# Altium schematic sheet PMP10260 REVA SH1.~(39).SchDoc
size 431 x 279 mm; Date: Not shown in title block; ApprovedBy: Not shown in title block; CheckedBy: Not shown in title block; Author: Not shown in title block; CompanyName: Not shown in title block; Engineer: Not shown in title block; Organization: Not shown in title block; Address1: Not shown in title block; Address2: Not shown in title block; Address3: Not shown in title block; Address4: Not shown in title block; DocumentNumber: 1; Revision: Use project parameter SCH_Rev; SheetNumber: 1; SheetTotal: 4; PageSetup: Record=PageOptions|CenterHorizontal=True|CenterVertical=True|PrintScale=1.00|XCorrection=1.00|YCorrection=1.00|PrintKind=0|BorderSize=5000000|LeftOffset=0|BottomOffset=0|Orientation=2|PaperLength=1000|PaperWidth=1000|Scale=100|PaperSource=15|PrintQuality=600|MediaType=1|DitherType=10|PaperKind=Letter|PrintScaleMode=1
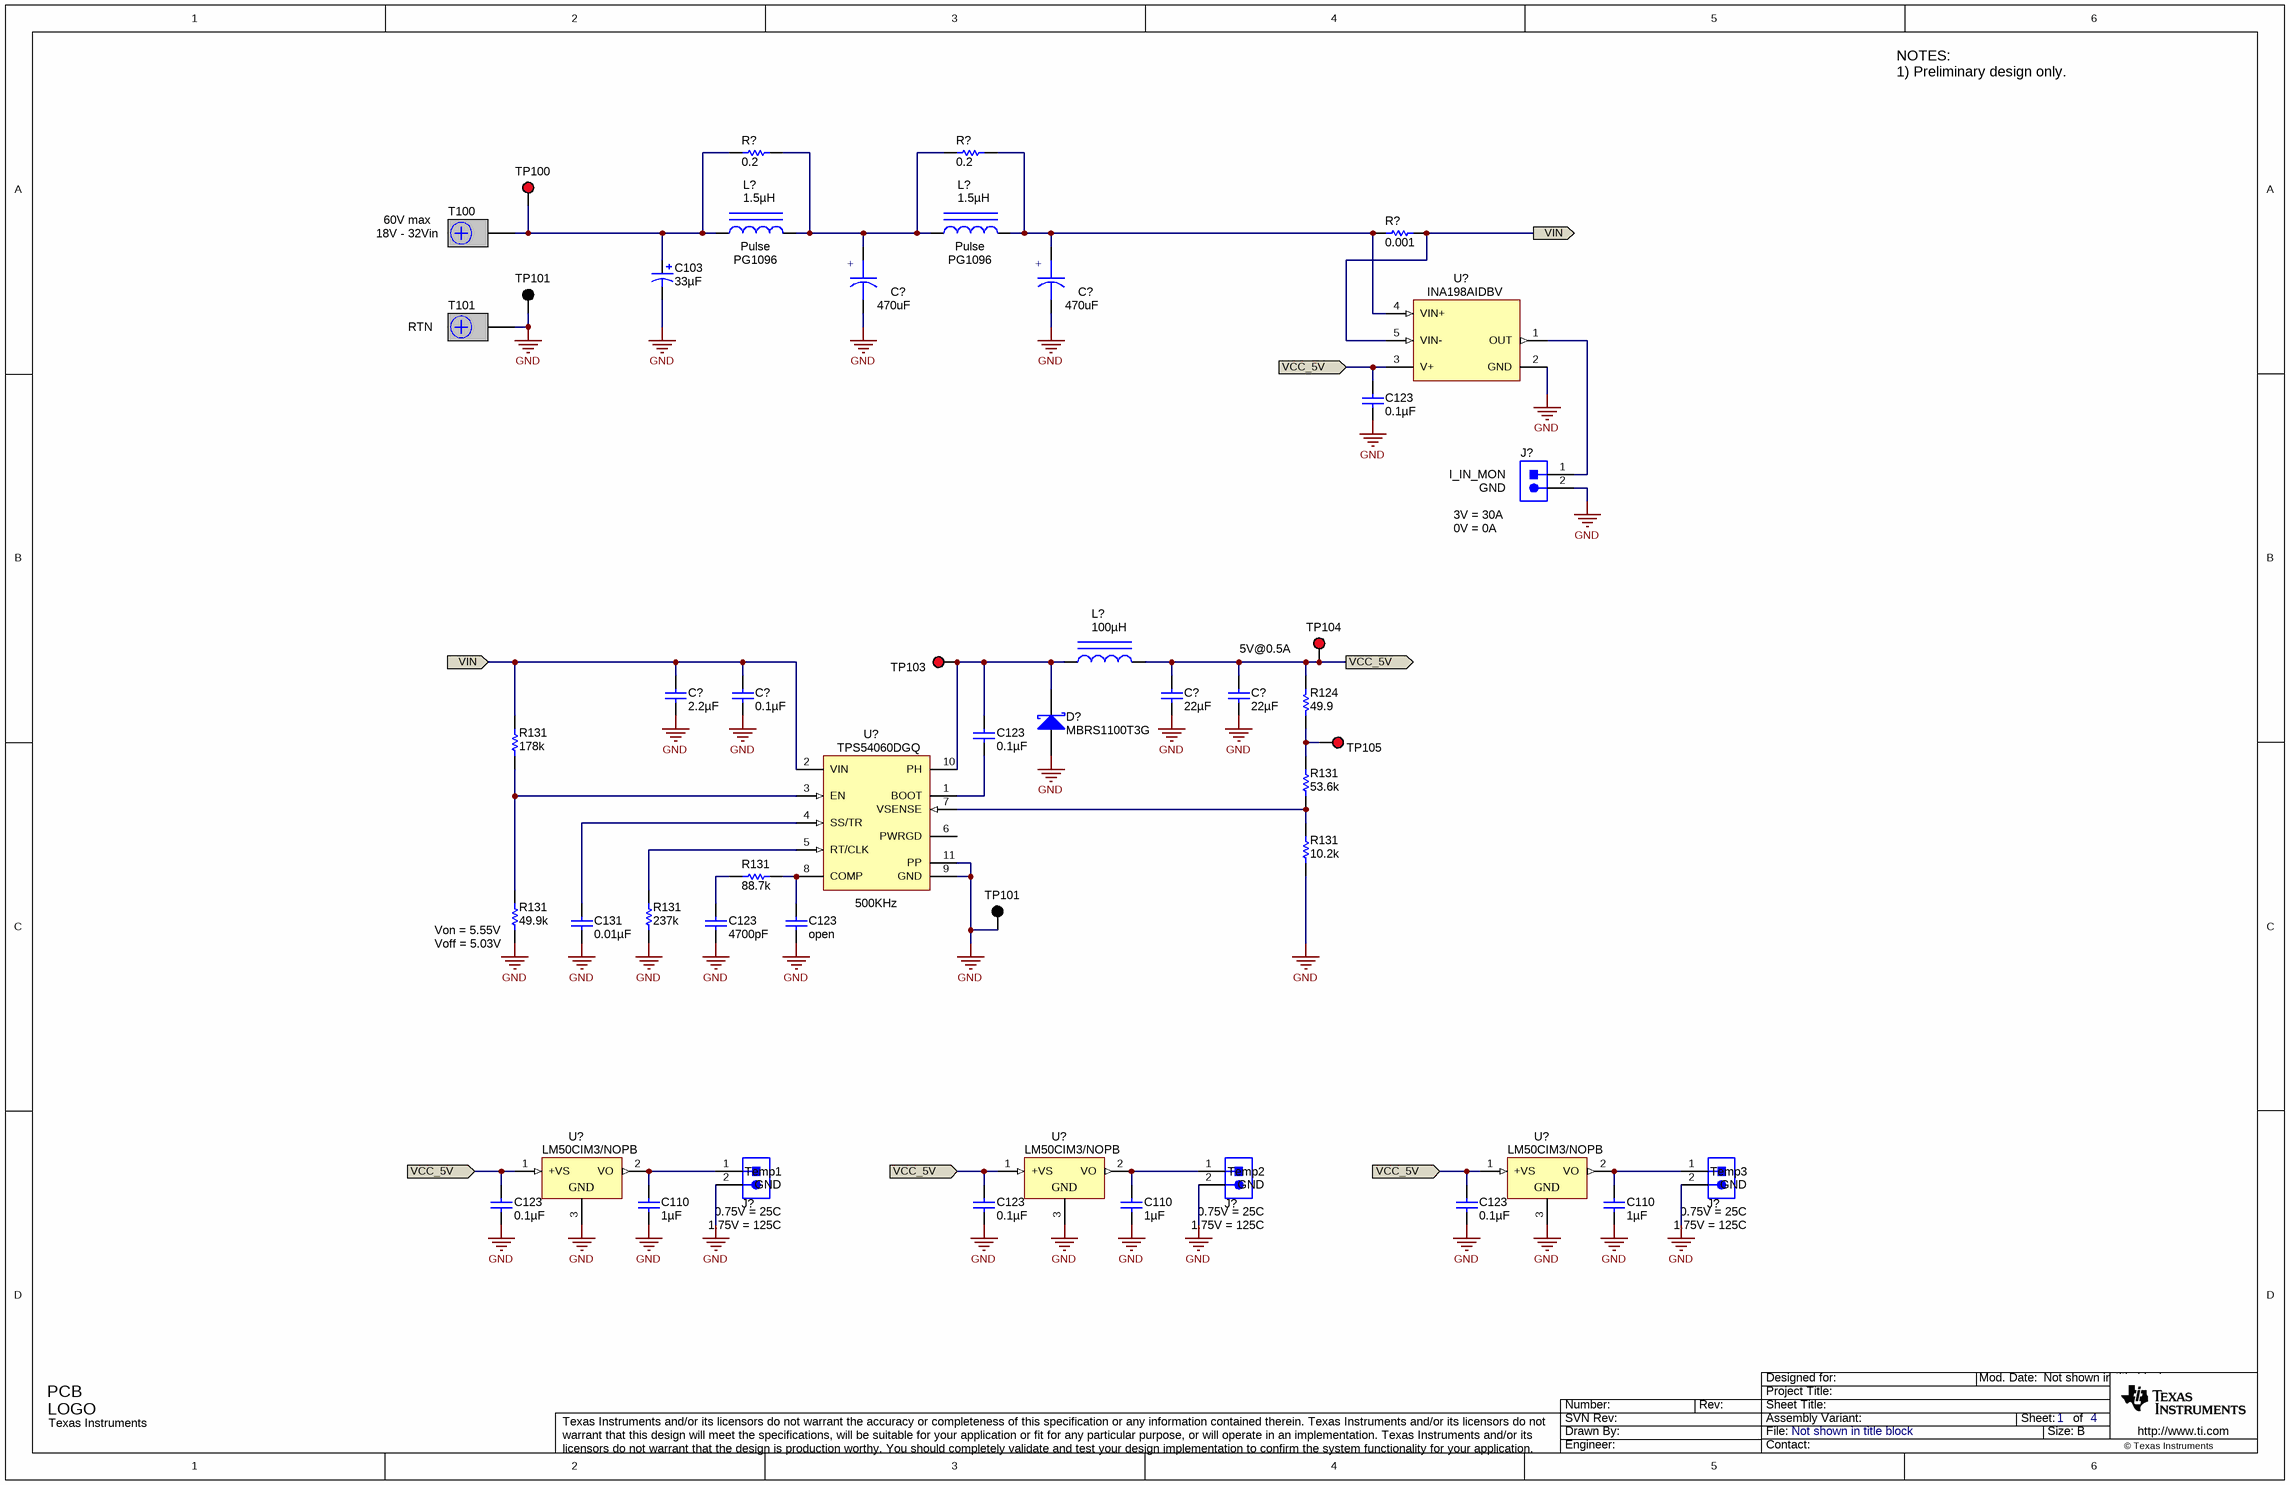
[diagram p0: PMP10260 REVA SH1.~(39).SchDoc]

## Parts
(Parts that share a designator on the sheet are numbered #1, #2 ... from top to bottom, then left to right.)
C103  ValueDisplayed: 33µF  [SXV_E12]  (hidden comment: 63SXV33M)
C110#1  ValueDisplayed: 1µF  [0603L]  (hidden comment: C1608X7R1E105K080AB)
C110#2  ValueDisplayed: 1µF  [0603L]  (hidden comment: C1608X7R1E105K080AB)
C110#3  ValueDisplayed: 1µF  [0603L]  (hidden comment: C1608X7R1E105K080AB)
C123#1  ValueDisplayed: 0.1µF  [0603L]  (hidden comment: C1608X7R1H104K)
C123#2  ValueDisplayed: 0.1µF  [0603L]  (hidden comment: C1608X7R1H104K)
C123#3  ValueDisplayed: 4700pF  [0603]  (hidden comment: C1608C0G1H472J)
C123#4  ValueDisplayed: open  [0603L]
C123#5  ValueDisplayed: 0.1µF  [0603L]  (hidden comment: C1608X7R1H104K)
C123#6  ValueDisplayed: 0.1µF  [0603L]  (hidden comment: C1608X7R1H104K)
C123#7  ValueDisplayed: 0.1µF  [0603L]  (hidden comment: C1608X7R1H104K)
C131  ValueDisplayed: 0.01µF  [0603]  (hidden comment: C1608X7R1H103K)
C?#1  value 470uF  [CAP_ZL-5X12.5MM]  (hidden comment: 63ZLH470M12.5x25)
C?#2  value 470uF  [CAP_ZL-5X12.5MM]  (hidden comment: 63ZLH470M12.5x25)
C?#3  ValueDisplayed: 2.2µF  [1210]  (hidden comment: GRM32ER72A225KA35L)
C?#4  ValueDisplayed: 0.1µF  [0603]  (hidden comment: GRM188R72A104KA35D)
C?#5  ValueDisplayed: 22µF  [1210]  (hidden comment: C3225X7R1C226M)
C?#6  ValueDisplayed: 22µF  [1210]  (hidden comment: C3225X7R1C226M)
D?  MBRS1100T3G  [SMB]
J?#1  PEC02SAAN  [CONN_PEC02SAAN]  (value not drawn)
J?#2  PEC02SAAN  [CONN_PEC02SAAN]  (value not drawn)
J?#3  PEC02SAAN  [CONN_PEC02SAAN]  (value not drawn)
J?#4  PEC02SAAN  [CONN_PEC02SAAN]  (value not drawn)
L?#1  ValueDisplayed: 1.5µH  [SER2918]
L?#2  ValueDisplayed: 1.5µH  [SER2918]
L?#3  ValueDisplayed: 100µH  [MSS1048]  (hidden comment: MSS1048-104MLB)
Logo100  Texas Instruments  [TI_Stacked_Overlay_Small]  (no BOM)
R124  value 49.9  [0603]  (hidden comment: CRCW060349R9FKEA)
R131#1  value 178k  [0603]  (hidden comment: CRCW0603178KFKEA)
R131#2  value 53.6k  [0603]  (hidden comment: CRCW060353K6FKEA)
R131#3  value 10.2k  [0603]  (hidden comment: CRCW060310K2FKEA)
R131#4  value 88.7k  [0603]  (hidden comment: CRCW060388K7FKEA)
R131#5  value 49.9k  [0603]  (hidden comment: CRCW060349K9FKEA)
R131#6  value 237k  [0603]  (hidden comment: CRCW0603237KFKEA)
R?#1  value 0.2  [2512M]  (hidden comment: WSL2512R2000FEA)
R?#2  value 0.2  [2512M]  (hidden comment: WSL2512R2000FEA)
R?#3  value 0.001  [CSS2725_0005]  (hidden comment: CSS2725FT1L00)
T100  CB35-36-CY  [CB35-36-CY]  (value not drawn)
T101  CB35-36-CY  [CB35-36-CY]  (value not drawn)
TP100  5010  [Keystone5010]  (value not drawn)
TP101#1  5011  [Keystone5011]  (value not drawn)
TP101#2  5011  [Keystone5011]  (value not drawn)
TP103  5010  [Keystone5010]  (value not drawn)
TP104  5010  [Keystone5010]  (value not drawn)
TP105  5010  [Keystone5010]  (value not drawn)
U?#1  INA198AIDBV  [DBV0005A_N]
U?#2  TPS54060DGQ  [DGQ0010D_N]
U?#3  LM50CIM3/NOPB  [MF03A_N]
U?#4  LM50CIM3/NOPB  [MF03A_N]
U?#5  LM50CIM3/NOPB  [MF03A_N]

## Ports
VCC_5V, VIN

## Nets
GND: C103.2(-) C110#1.2 C110#2.2 C110#3.2 C123#1.2 C123#3.2 C123#4.2 C123#5.2 C123#6.2 C123#7.2 C131.2 C?#1.2 C?#2.2 C?#3.2 C?#4.2 C?#5.2 C?#6.2 D?.2(A) J?#1.2 J?#2.2 J?#3.2 J?#4.2 R131#3.1 R131#5.1 R131#6.1 T101.1 TP101#1.1 TP101#2.1 U?#1.2(GND) U?#2.9(GND) U?#2.11(PP) U?#3.3(GND) U?#4.3(GND) U?#5.3(GND)
VCC_5V: C123#1.1 C123#5.1 C123#6.1 C123#7.1 C?#5.1 C?#6.1 L?#3.2 R124.2 TP104.1 U?#1.3(V+) U?#3.1(+VS) U?#4.1(+VS) U?#5.1(+VS) ; port VCC_5V
VIN: C?#3.1 C?#4.1 R131#1.2 R?#3.2 U?#1.5(VIN-) U?#2.2(VIN) ; port VIN
NetC103_1: C103.1(+) L?#1.1 R?#1.1 T100.1 TP100.1
NetC110#1_1: C110#1.1 J?#2.1 U?#3.2(VO)
NetC110#2_1: C110#2.1 J?#3.1 U?#4.2(VO)
NetC110#3_1: C110#3.1 J?#4.1 U?#5.2(VO)
NetC123#2_1: C123#2.1 D?.1(K) L?#3.1 TP103.1 U?#2.10(PH)
NetC123#2_2: C123#2.2 U?#2.1(BOOT)
NetC123#3_1: C123#3.1 R131#4.2
NetC123#4_1: C123#4.1 R131#4.1 U?#2.8(COMP)
NetC131_1: C131.1 U?#2.4(SS/TR)
NetC?#1_1: C?#1.1 L?#1.2 L?#2.1 R?#1.2 R?#2.1
NetC?#2_1: C?#2.1 L?#2.2 R?#2.2 R?#3.1 U?#1.4(VIN+)
NetJ?#1_1: J?#1.1 U?#1.1(OUT)
NetR124_1: R124.1 R131#2.2 TP105.1
NetR131#1_1: R131#1.1 R131#5.2 U?#2.3(EN)
NetR131#2_1: R131#2.1 R131#3.2 U?#2.7(VSENSE)
NetR131#6_2: R131#6.2 U?#2.5(RT/CLK)

Not connected (* = marked no-connect by the designer): U?#2 6(PWRGD)

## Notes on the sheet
- NOTES:
  1) Preliminary design only.
- (near T100) 18V - 32Vin
- 60V max
- (near L?#1) Pulse
- (near L?#1) PG1096
- (near L?#2) Pulse
- (near L?#2) PG1096
- RTN
- (near J?#1) I_IN_MON
- (near J?#1) GND
- (near J?#1) 3V = 30A
- 0V = 0A
- 5V@0.5A
- (near U?#2) 500KHz
- (near R131#5) Von = 5.55V
- (near R131#5) Voff = 5.03V
- (near J?#2) Temp1
- (near J?#3) Temp2
- (near J?#4) Temp3
- (near J?#2) 0.75V = 25C
- (near J?#2) 1.75V = 125C
- (near J?#2) GND
- (near J?#3) 0.75V = 25C
- (near J?#3) 1.75V = 125C
- (near J?#3) GND
- (near J?#4) 0.75V = 25C
- (near J?#4) 1.75V = 125C
- (near J?#4) GND

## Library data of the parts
C103 = 63SXV33M: CAP, OS-CON, 33uF, 63V, +/-20%, 0.025 ohm, 8.0x11.9mm SMD; Manufacturer: Panasonic; Polarized: Y; CompType: Capacitor; U/M: EA; Cap_F: 0.000033; Tolerance_%: 20; VDC_V: 63; ESR_Ohm: 0.025; IRMS_A: 2.95; TaMin_C: -55; TaMax_C: 105
C110#1-C110#3 = C1608X7R1E105K080AB: CAP, CERM, 1uF, 25V, +/-10%, X7R, 0603; Manufacturer: TDK; Polarized: N; CompType: Capacitor; U/M: EA; Cap_F: 0.000001; Tolerance_%: 10; Value1: Unknown; VDC_V: 25; TaMin_C: -55; TaMax_C: 125; Cap_Case: 0603
C123#1 C123#2 C123#5-C123#7 = C1608X7R1H104K: CAP, CERM, 0.1uF, 50V, +/-10%, X7R, 0603; Manufacturer: TDK; Polarized: N; CompType: Capacitor; U/M: EA; Cap_F: 0.0000001; Tolerance_%: 10; ESR_Ohm: 0.017; Value1: 0.017 ohm; VDC_V: 50; TaMin_C: -55; TaMax_C: 125; Cap_Case: 0603
C123#3 = C1608C0G1H332J: CAP, CERM, 4700pF, 50V, +/-5%, C0G/NP0, 0603; Manufacturer: TDK; Polarized: N; CompType: Capacitor; Value: 3300pF; U/M: EA; Cap_F: 0.0000000033; Tolerance_%: 5; ESR_Ohm: 0.0309; Value1: 0.0309 ohm; VDC_V: 50; TaMin_C: -55; TaMax_C: 125
C123#4 = C1608X7R1H104K: CAP, open, 0603; Polarized: N; CompType: Capacitor; U/M: EA; Cap_F: 0.0000001; Tolerance_%: 10; ESR_Ohm: 0.017; TempCo: X7R; TaMin_C: -55; TaMax_C: 125; Cap_Case: 0603
C131 = C1608X7R1H103K: CAP, CERM, 0.01uF, 50V, +/-10%, X7R, 0603; Manufacturer: TDK; Polarized: N; CompType: Capacitor; U/M: EA; Cap_F: 0.00000001; Tolerance_%: 10; ESR_Ohm: 0.0539; Value1: 0.0539 ohm; VDC_V: 50; TaMin_C: -55; TaMax_C: 125
C?#1 C?#2 = CAP_ZL_12.5MM_SERIES: Capacitor, multi pattern, SM 1210 to E case + F THole; Manufacturer: Rubycon; Area: 214,008
C?#3 = GRM32ER72A225KA35L: CAP, CERM, 2.2uF, 100V, +/-10%, X7R, 1210; Manufacturer: MuRata; Polarized: N; CompType: Capacitor; U/M: EA; Cap_F: 0.0000022; Tolerance_%: 10; ESR_Ohm: 0.007; Value1: 0.007 ohm; VDC_V: 100; IRMS_A: 4.4; TaMin_C: -55; TaMax_C: 125
C?#4 = GRM188R72A104KA35D: CAP, CERM, 0.1uF, 100V, +/-10%, X7R, 0603; Manufacturer: MuRata; Polarized: N; CompType: Capacitor; U/M: EA; Cap_F: 0.0000001; Tolerance_%: 10; Value1: Unknown; VDC_V: 100; TaMin_C: -55; TaMax_C: 125
C?#5 C?#6 = C3225X7R1C226M: CAP, CERM, 22uF, 16V, +/-20%, X7R, 1210; Manufacturer: TDK; Polarized: N; CompType: Capacitor; U/M: EA; Cap_F: 0.000022; Tolerance_%: 20; ESR_Ohm: 0.002; Value1: 0.002 ohm; VDC_V: 16; IRMS_A: 8.11; TaMin_C: -55; TaMax_C: 125
D? = MBRS1100T3G: Diode, Schottky, 100V, 1A, SMB; Manufacturer: ON Semiconductor; U/M: EA; Vf_V: 0.75; Value2: 0.75V; Io_A: 1; Vr_V: 100; TJmax_C: 150; RJC_CperW: 22
J?#1-J?#4 = PEC02SAAN: Header, 100mil, 2x1, Tin, TH; Manufacturer: Sullins Connector Solutions; SymbolCreator: a0412235; U/M: EA
L?#1 L?#2 = SER2918H-332KL: Inductor, Shielded E Core, Ferrite, 3.3uH, 28A, 0.0026 ohm, SMD; Manufacturer: Pulse; Ind_H: 3.3E-6; Imax_A: 28; Irms: 28A @ 40C rise; Isat: 93.6A @ 30% inductance drop; DCR_ohm: 0.0026
L?#3 = MSS1048-104MLB: Inductor, Shielded Drum Core, Ferrite, 100uH, 1.36A, 0.25 ohm, SMD; Manufacturer: Coilcraft; Ind_H: 100.0E-6; Imax_A: 1.36; Irms: 1.48A @ 40C rise; Isat: 1.36A @ 30% inductance drop; DCR_ohm: 0.25
Logo100 = TI_Logo: Texas Instrument Corporate Signature; SymbolCreator: codlsc
R124 = CRCW060349R9FKEA: RES, 49.9 ohm, 1%, 0.1W, 0603; Manufacturer: Vishay-Dale; CompType: Resistor; Value_Code: 49R9; Tolerance_%: 1; Power_W: 0.1; VDC_V: 75; TempCo: 100 ppm/C; EIA_Code: E96; U/M: EA
R131#1 = CRCW0603178KFKEA: RES, 178k ohm, 1%, 0.1W, 0603; Manufacturer: Vishay-Dale; CompType: Resistor; Res_ohm: 178000; Tolerance_%: 1; Power_W: 0.1; VDC_V: 75; TempCo: 100 ppm/C; EIA_Code: E96; U/M: EA
R131#2 = CRCW060353K6FKEA: RES, 53.6k ohm, 1%, 0.1W, 0603; Manufacturer: Vishay-Dale; CompType: Resistor; Res_ohm: 53600; Value_Code: 53k6; Tolerance_%: 1; Power_W: 0.1; VDC_V: 75; TempCo: 100 ppm/C; EIA_Code: E96; U/M: EA
R131#3 = CRCW060310K2FKEA: RES, 10.2k ohm, 1%, 0.1W, 0603; Manufacturer: Vishay-Dale; CompType: Resistor; Res_ohm: 10200; Value_Code: 10k2; Tolerance_%: 1; Power_W: 0.1; VDC_V: 75; TempCo: 100 ppm/C; EIA_Code: E96; U/M: EA
R131#4 = CRCW060388K7FKEA: RES, 88.7k ohm, 1%, 0.1W, 0603; Manufacturer: Vishay-Dale; CompType: Resistor; Res_ohm: 88700; Value_Code: 88k7; Tolerance_%: 1; Power_W: 0.1; VDC_V: 75; TempCo: 100 ppm/C; EIA_Code: E96; U/M: EA
R131#5 = CRCW060349K9FKEA: RES, 49.9k ohm, 1%, 0.1W, 0603; Manufacturer: Vishay-Dale; CompType: Resistor; Res_ohm: 49900; Value_Code: 49k9; Tolerance_%: 1; Power_W: 0.1; VDC_V: 75; TempCo: 100 ppm/C; EIA_Code: E96; U/M: EA
R131#6 = CRCW0603237KFKEA: RES, 237k ohm, 1%, 0.1W, 0603; Manufacturer: Vishay-Dale; CompType: Resistor; Res_ohm: 237000; Tolerance_%: 1; Power_W: 0.1; VDC_V: 75; TempCo: 100 ppm/C; EIA_Code: E96; U/M: EA
R?#1 R?#2 = WSL2512R2000FEA: RES, 0.2 ohm, 1%, 1W, 2512; Manufacturer: Vishay-Dale; CompType: Resistor; Value_Code: R200; Tolerance_%: 1; VDC_V: 0.45; TempCo: 75 ppm/C; EIA_Code: E96; U/M: EA
R?#3 = CSS2725FTL500: RES, 0.001 ohm, 1%, 4W, RES_2725; Manufacturer: Stackpole Electronics Inc; CompType: Resistor; Res_ohm: 0.0005; Value_Code: R001; Tolerance_%: 1; Power_W: 4; TempCo: 50 ppm/C; U/M: EA
T100 T101 = CB35-36-CY: Terminal 50A Lug; Manufacturer: Panduit; SymbolCreator: crossc; CompType: Screw Terminal; U/M: EA
TP100 TP103-TP105 = 5010: Test Point, Multipurpose, Red, TH; Manufacturer: Keystone; CompType: Test Point Loop; U/M: EA
TP101#1 TP101#2 = 5011: Test Point, Multipurpose, Black, TH; Manufacturer: Keystone; CompType: Test Point Loop; U/M: EA
U?#1 = INA198AIDBV: CURRENT SHUNT MONITOR -16V to +80V Common-Mode Range, DBV0005A; Alternate Manufacturer: None; Manufacturer: Texas Instruments; SymbolCreator: a0411947; CompType: IC; U/M: EA
U?#2 = TPS54060DGQ: Buck Inverting Buck-Boost Step Down Regulator with 3.5 to 60 V Input and 0.8 to 58 V Output, -40 to 150 degC, 10-Pin MSOP-PowerPAD (DGQ), Green (RoHS & no Sb/Br); Manufacturer: Texas Instruments; Alternate Manufacturer: None; Alternate PartNumber: Equivalent; Duty Cycle(Max)(%): 98; Iout(Max)(A): 0.5; Iq(Typ)(mA): 0.116; Rating: Catalog; Regulated Outputs(#): 1; SubFamily: Step-Down Regulator; Switch Current Limit(Typ)(A): 0.6; Topology: Buck, Inverting Buck-Boost; Vin(Max)(V): 60; Vin(Min)(V): 3.5; Vout(Max)(V): 58; Vout(Min)(V): 0.8
U?#3-U?#5 = LM50CIM3/NOPB: Single-Supply Centigrade Temperature Sensor, 3-pin SOT-23, Pb-Free; Manufacturer: Texas Instruments; PackageTopMarking: T5C*XTT; PowerWise: N; CompType: Temp Sensor IC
